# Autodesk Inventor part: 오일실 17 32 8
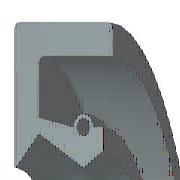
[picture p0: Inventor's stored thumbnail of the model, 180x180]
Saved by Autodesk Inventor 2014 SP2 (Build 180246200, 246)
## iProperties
IsCustomPart: 1
Created: 2012-02
Part Number: 오일실 17 32 8
Material: 고무
Description: 오일-실
Document SubType Name: Modeling
Standard: KS B 2804
Designer: mduedu
Standards Organization: KS
Language: ko-KR
Size Designation: D - 17 32 8
Categories: <MemberInstance><Categories><Category DisplayName="샤프트 부품" InternalName="7f7aeb1f-a693-4053-b835-cee3144e0d98" Mnemonic="SHFT"><Category DisplayName="실링" Intern
Density: 0.93 g/cm^3
Appearance: 고무 - 검은색 - 버전 1.1
Author: mduedu
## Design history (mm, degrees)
revolve "본체" stored, may be unused: angle "d17" = 90 deg
revolve "스프링1" stored, may be unused: angle "d18" = 90 deg
body "Solid1"
sketch "스케치1"
  geometry: L1 (0, 16)-(8, 16); L2 (8, 14.25)-(1.75, 14.25); L3 (1.75, 10.25)-(4.9, 8.5); L4 (4.9, 8.5)-(0, 8.5); L5 (0, 0)-(9.586, 0) reference; L6 (4.9, 8.5)-(6.3, 9.375); L7 (0, 18)-(0, -3) reference; L8 (-1.941, 0)-(11.507, 0) reference; L9 (4.2, 10.6)-(1.75, 11.21); L10 (1.75, 11.21)-(1.75, 14.25); L11 (0, 16)-(0, 8.588); L12 (4.9, 8.5)-(0, 8.5); L13 (1.75, 10.25)-(0.152, 8.528); L14 (8, 16)-(8, 14.25); L15 (5.6, 10.6)-(6.3, 10.6); L16 (6.3, 10.6)-(6.3, 9.375); C1 r 0.455 at (4.9, 10.6); A1 r 0.7 centre (4.9, 10.6) between (5.6, 10.6) and (4.2, 10.6); A2 r 0.088 centre (0.088, 8.588) between (0, 8.588) and (0.152, 8.528); 1 further point
  constraints: 28 end point, 5 horizontal alignment, 5 point on line, 4 point on circle, 4 vertical alignment, 3 centre point, 3 tangent, 2 collinear, 2 horizontal, 2 perpendicular, 1 coincident, 1 parallel
  dimensions: "d0" = 32 diameter of L1 L5 (= SD2); "d1" = 1.75 distance of L1.end L2.start (= SD); "d2" = 0.91 diameter of C1 (= SPDI); "d3" = 1.4 diameter of A1 (= SPDA); "d4" = 17 diameter of L3.end L5 (= NND); "d5" = 20.5 diameter of L3.start L5 (= TKDM); "d7" = 22.42 diameter of L9.end L5 (= TKDM + 0.24 x SWDT); "d8" = 1.75 distance between parallel lines of L11 L10 (= SD); "d9" = 4.9 distance from line of L11 C1.centre (= SPDST); "d10" = 21.2 diameter of C1.centre L5 (= HLDM); "d11" = 0.0875 radius of A2 (= 0.25 x LAB); "d12" = 6.3 distance between parallel lines of L11 L16 (= SDI); "d13" = 18.75 diameter of L6.end L5 (= ABDM); "d14" = 8 distance from line of L11 L1.end (= SWDT)
fillet "모깎기1" dims "d6" = 0.3 (= RR)
other parameters: "SD2" = 32 [user parameter; used in 1 equation term], "SWDT" = 8 [user parameter; used in 2 equation terms], "RR" = 0.3 [user parameter; used in 1 equation term], "SD" = 1.75 [user parameter; used in 2 equation terms], "NND" = 17 [user parameter; used in 1 equation term], "SPDA" = 1.4 [user parameter; used in 1 equation term], "SPDI" = 0.91 [user parameter; used in 1 equation term], "TKDM" = 20.5 [user parameter; used in 2 equation terms], "HLDM" = 21.2 [user parameter; used in 1 equation term], "ABDM" = 18.75 [user parameter; used in 1 equation term], "SDI" = 6.3 [user parameter; used in 1 equation term], "SPDST" = 4.9 [user parameter; used in 1 equation term], "LAB" = 0.35 [user parameter; used in 1 equation term], "d15" = 0, "d16" = 0, "d19" = 0
